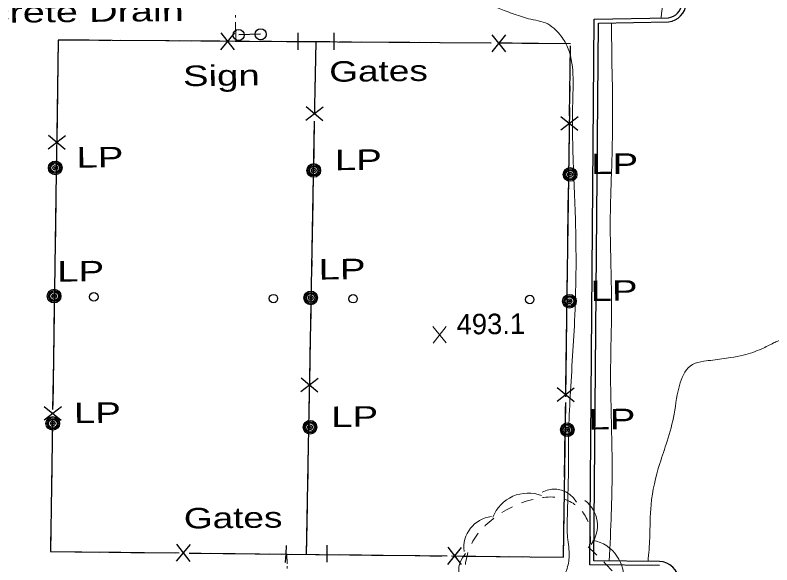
# Model space of a CAD drawing. Extents: x 2362213 to 2366494, y 6968794 to 6978110.
# Drawn here: x 2364059.7 to 2364237.1, y 6972028.3 to 6972157.2 of the extents above; entities that cross this region are included whole.
import ezdxf

# ---------------------------------------------------------------- set-up
doc = ezdxf.new("R2010")
doc.units = 0
doc.header["$LTSCALE"] = 1.9
for name, pattern in [('DOTTED', [1.5, 0.3, -1.2]), ('LONG_DASH_SHORT_DASH', [9.9, 6, -1.2, 1.5, -1.2]), ('SHORT_DASHED', [2.7, 1.5, -1.2])]:
    doc.linetypes.add(name, pattern=pattern)
for name, color, linetype, lineweight in [('13', 7, 'Continuous', 13), ('17', 7, 'Continuous', 25), ('2', 7, 'Continuous', 25), ('20', 7, 'Continuous', 25), ('21', 7, 'Continuous', 25), ('28', 7, 'Continuous', 13), ('29', 7, 'Continuous', 13), ('31', 7, 'Continuous', 25), ('35', 7, 'Continuous', 13)]:
    doc.layers.add(name, color=color, linetype=linetype, lineweight=lineweight)

msp = doc.modelspace()

# ---------------------------------------------------------------- linework, layer by layer
at = {"layer": '13'}
for p, q in [((2364111.329, 6972155.527), (2364111.377, 6972151.527)), ((2364123.43, 6972028.555), (2364123.338, 6972030.825))]:
    msp.add_line(p, q, dxfattribs=at)
at = {"layer": '13', "linetype": 'DOTTED'}
for points in [[(2364110.001, 6972194.146), (2364120.962, 6972182.64), (2364120.484, 6972160.274), (2364111.286, 6972160.077), (2364111.382, 6972151.057)], [(2364214.461, 6972024.613), (2364193.147, 6972026), (2364189.473, 6972021.205), (2364123.705, 6972021.739), (2364123.338, 6972030.825)]]:
    msp.add_lwpolyline(points, dxfattribs=at)
at = {"layer": '17'}
for p, q in [((2364111.063, 6972153.034), (2364107.841, 6972149.053)), ((2364107.863, 6972153.054), (2364111.041, 6972149.034)), ((2364174.66, 6972152.58), (2364171.438, 6972148.609)), ((2364171.47, 6972152.599), (2364174.638, 6972148.579)), ((2364171.249, 6972150.637), (2364111.252, 6972151.056)), ((2364130.144, 6972150.926), (2364129.867, 6972135.933)), ((2364189.852, 6972150.504), (2364174.849, 6972150.612)), ((2364189.673, 6972133.572), (2364189.906, 6972150.015)), ((2364127.829, 6972132.563), (2364131.889, 6972135.692)), ((2364127.888, 6972135.764), (2364131.829, 6972132.491)), ((2364191.645, 6972133.341), (2364187.605, 6972130.192)), ((2364191.606, 6972130.14), (2364187.644, 6972133.393)), ((2364129.801, 6972132.332), (2364128.692, 6972072.337)), ((2364067.459, 6972129.068), (2364071.41, 6972125.805)), ((2364188.798, 6972069.981), (2364189.627, 6972129.971)), ((2364067.41, 6972125.867), (2364071.46, 6972129.006)), ((2364069.372, 6972125.636), (2364068.463, 6972065.645)), ((2364126.654, 6972068.979), (2364130.714, 6972072.097)), ((2364126.714, 6972072.179), (2364130.655, 6972068.907)), ((2364128.626, 6972068.738), (2364127.918, 6972030.768)), ((2364190.771, 6972069.74), (2364186.729, 6972066.601)), ((2364190.731, 6972066.549), (2364186.769, 6972069.801)), ((2364066.445, 6972062.275), (2364070.495, 6972065.414)), ((2364066.495, 6972065.476), (2364070.446, 6972062.213)), ((2364097.522, 6972029.149), (2364100.765, 6972033.11)), ((2364100.723, 6972029.109), (2364097.564, 6972033.139)), ((2364161.122, 6972028.424), (2364164.364, 6972032.395)), ((2364164.322, 6972028.395), (2364161.164, 6972032.425)), ((2364100.945, 6972031.081), (2364160.943, 6972030.403))]:
    msp.add_line(p, q, dxfattribs=at)
at = {"layer": '17', "linetype": 'LONG_DASH_SHORT_DASH'}
msp.add_line((2364130.144, 6972150.926), (2364127.918, 6972030.768), dxfattribs=at)
at = {"layer": '17'}
for points in [[(2364126.011, 6972149.066), (2364126.002, 6972151.066), (2364125.993, 6972153.066)], [(2364134.364, 6972153.076), (2364134.363, 6972151.076), (2364134.362, 6972149.076)], [(2364107.651, 6972151.082), (2364069.767, 6972151.351), (2364069.428, 6972129.237)], [(2364164.543, 6972030.357), (2364188.258, 6972030.093), (2364188.753, 6972066.38)], [(2364068.407, 6972062.044), (2364067.949, 6972031.447), (2364097.343, 6972031.117)], [(2364123.087, 6972028.842), (2364123.198, 6972030.843), (2364123.309, 6972032.844)], [(2364132.728, 6972032.914), (2364132.737, 6972030.914), (2364132.746, 6972028.914)]]:
    msp.add_lwpolyline(points, dxfattribs=at)
at = {"layer": '17', "linetype": 'LONG_DASH_SHORT_DASH'}
msp.add_lwpolyline([(2364189.852, 6972150.504), (2364069.767, 6972151.351), (2364067.949, 6972031.447), (2364188.258, 6972030.093), (2364189.906, 6972150.015)], dxfattribs=at)
at = {"layer": '2'}
for points in [[(2364210.737, 6972028.167), (2364194.395, 6972028.311), (2364195.466, 6972156.228), (2364212.884, 6972156.604)], [(2364210.748, 6972029.127), (2364195.366, 6972029.26), (2364196.415, 6972155.287), (2364212.904, 6972155.644)]]:
    msp.add_lwpolyline(points, dxfattribs=at)
for centre, radius, start, end in [((2364212.41, 6972160.191), 3.614, 276.18661, 356.00812), ((2364212.41, 6972160.191), 4.574, 276.18661, 356.00812), ((2364210.375, 6972024.056), 5.085, 7.18498, 85.79573)]:
    msp.add_arc(centre, radius, start, end, dxfattribs=at)
at = {"layer": '20'}
for centre, radius in [((2364069.062, 6972121.393), 1.6), ((2364069.062, 6972121.393), 1.3), ((2364069.062, 6972121.393), 1), ((2364129.671, 6972120.79), 1.6), ((2364129.671, 6972120.79), 1.3), ((2364069.062, 6972121.393), 0.539), ((2364069.062, 6972121.393), 0.192), ((2364129.671, 6972120.79), 1), ((2364129.671, 6972120.79), 0.539), ((2364129.671, 6972120.79), 0.192), ((2364189.783, 6972119.862), 1.6), ((2364189.783, 6972119.862), 1.3), ((2364189.783, 6972119.862), 1), ((2364189.783, 6972119.862), 0.539), ((2364189.783, 6972119.862), 0.192), ((2364068.799, 6972091.319), 1.6), ((2364068.799, 6972091.319), 1.3), ((2364068.799, 6972091.319), 1), ((2364068.799, 6972091.319), 0.539), ((2364078.091, 6972091.147), 1), ((2364128.966, 6972090.902), 1.6), ((2364128.966, 6972090.902), 1.3), ((2364128.966, 6972090.902), 1), ((2364068.799, 6972091.319), 0.192), ((2364120.217, 6972090.728), 1), ((2364128.966, 6972090.902), 0.539), ((2364128.966, 6972090.902), 0.192), ((2364138.888, 6972090.716), 1), ((2364180.322, 6972090.521), 1), ((2364189.646, 6972090.119), 1.6), ((2364189.646, 6972090.119), 1.3), ((2364189.646, 6972090.119), 1), ((2364189.646, 6972090.119), 0.539), ((2364189.646, 6972090.119), 0.192), ((2364068.483, 6972061.484), 1.6), ((2364068.483, 6972061.484), 1.3), ((2364068.483, 6972061.484), 1), ((2364068.483, 6972061.484), 0.539), ((2364068.483, 6972061.484), 0.192), ((2364128.804, 6972060.579), 1.6), ((2364128.804, 6972060.579), 1.3), ((2364128.804, 6972060.579), 1), ((2364128.804, 6972060.579), 0.539), ((2364128.804, 6972060.579), 0.192), ((2364189.133, 6972059.983), 1.6), ((2364189.133, 6972059.983), 1.3), ((2364189.133, 6972059.983), 1), ((2364189.133, 6972059.983), 0.539), ((2364189.133, 6972059.983), 0.192)]:
    msp.add_circle(centre, radius, dxfattribs=at)
at = {"layer": '21'}
msp.add_line((2364117.226, 6972152.733), (2364112.097, 6972152.554), dxfattribs=at)
for centre in [(2364117.217, 6972152.722), (2364112.088, 6972152.544)]:
    msp.add_circle(centre, 1.3, dxfattribs=at)
at = {"layer": '29'}
for centre, radius, start, end in [((2364186.112, 6972040.189), 5.889, 28.74305, 118.74305), ((2364179.948, 6972036.298), 8.839, 68.94138, 158.94138), ((2364188.833, 6972037.522), 7.369, 323.00429, 53.00429), ((2364172.23, 6972032.337), 7.369, 96.88937, 186.88937), ((2364193.498, 6972025.384), 8.839, 349.43512, 79.43512), ((2364169.555, 6972026.926), 5.889, 136.99099, 226.99099)]:
    msp.add_arc(centre, radius, start, end, dxfattribs=at)
at = {"layer": '29', "linetype": 'SHORT_DASHED'}
msp.add_spline([(2364193.995, 6972032.548), (2364202.775, 6972023.042), (2364208.45, 6972003.624), (2364204.259, 6971991.114), (2364199.061, 6971985.644), (2364199.653, 6971976.01), (2364204.763, 6971960.237), (2364194.81, 6971943.811), (2364177.187, 6971948.135), (2364166.75, 6971965.755), (2364170.786, 6971984.024), (2364170.369, 6971996.262), (2364166.915, 6972014.51), (2364166.041, 6972031.781), (2364180.718, 6972043.563), (2364189.382, 6972043.355), (2364193.928, 6972038.578), (2364194.541, 6972033.013)], degree=3, dxfattribs=at)
at = {"layer": '31', "lineweight": 13}
for p, q in [((2364160.757, 6972080.354), (2364157.64, 6972084.205)), ((2364157.677, 6972080.325), (2364160.72, 6972084.234))]:
    msp.add_line(p, q, dxfattribs=at)
at = {"layer": '35'}
for points in [[(2364217.742, 6972294.317), (2364217.129, 6972289.46), (2364216.268, 6972279.113), (2364215.551, 6972268.304), (2364214.768, 6972258.098), (2364214.429, 6972244.393), (2364214.09, 6972231.659), (2364214.046, 6972206.827), (2364213.077, 6972182.627), (2364212.025, 6972164.976), (2364211.145, 6972156.567)], [(2364091.503, 6972164.529), (2364100.213, 6972163.581), (2364103.636, 6972163.174), (2364111.989, 6972162.874), (2364117.079, 6972163.992), (2364122.147, 6972164.31), (2364134.281, 6972163.866), (2364140.814, 6972163.568), (2364150.574, 6972163.601), (2364160.268, 6972163.213), (2364161.13, 6972163.001), (2364164.749, 6972162.056), (2364166.909, 6972161.166), (2364171.204, 6972159.567), (2364174.356, 6972158.297), (2364178.128, 6972156.963), (2364180.024, 6972156.361), (2364184.536, 6972155.134), (2364186.43, 6972153.702), (2364188.648, 6972150.833), (2364190.4, 6972137.039), (2364190.488, 6972123.558), (2364191.078, 6972107.794), (2364190.85, 6972085.511), (2364189.749, 6972066.71), (2364189.45, 6972058.226), (2364189.401, 6972050.775), (2364189.125, 6972038.772), (2364189.158, 6972035.323), (2364189.581, 6972030.845), (2364189.093, 6972027.491), (2364188.001, 6972023.531), (2364188.282, 6972020.274), (2364184.272, 6972020.125), (2364174.98, 6972020.217), (2364168.57, 6972020.326), (2364162.308, 6972020.406), (2364155.958, 6972019.286)], [(2364199.535, 6972155.357), (2364199.546, 6972149.947), (2364199.753, 6972137.678), (2364199.568, 6972122.495), (2364199.212, 6972108.402), (2364199.525, 6972088.124), (2364199.294, 6972074.58), (2364199.628, 6972054.162), (2364199.46, 6972040.381), (2364198.946, 6972029.225)], [(2364239.855, 6972081.057), (2364238.518, 6972080.785), (2364237.522, 6972080.335), (2364234.755, 6972078.988), (2364230.408, 6972077.456), (2364227.493, 6972076.909), (2364225.386, 6972076.578), (2364221.121, 6972076.048), (2364218.479, 6972075.283), (2364215.63, 6972070.976), (2364214.18, 6972063.652), (2364212.54, 6972057.305), (2364210.83, 6972052.049), (2364208.771, 6972042.41), (2364208.465, 6972034.585), (2364208.067, 6972029.151)]]:
    msp.add_spline(points, degree=3, dxfattribs=at)

# ---------------------------------------------------------------- texts
at = {"layer": '17', "width": 1.35}
for p in [(2364133.333, 6972141.566), (2364099.24, 6972036.826)]:
    msp.add_text('Gates', height=4.8, rotation=0.546, dxfattribs=at).set_placement(p)
at = {"layer": '20', "width": 1.4}
for p in [(2364069.062, 6972121.392), (2364129.671, 6972120.789), (2364189.783, 6972119.861), (2364064.557, 6972094.668), (2364125.855, 6972095.153), (2364189.647, 6972090.12), (2364068.483, 6972061.485), (2364128.804, 6972060.579), (2364189.133, 6972059.983)]:
    msp.add_text('  LP', height=4.8, rotation=0.546, dxfattribs=at).set_placement(p)
at = {"layer": '21', "width": 1.4}
msp.add_text('Sign', height=4.8, rotation=0.546, dxfattribs=at).set_placement((2364099.042, 6972140.549))
at = {"layer": '28', "width": 1.45}
msp.add_text('Concrete Drain', height=4.8, rotation=0.546, dxfattribs=at).set_placement((2364036.639, 6972155.226))
at = {"layer": '31'}
msp.add_text('493.1', height=4.8, rotation=0.546, dxfattribs=at).set_placement((2364163.199, 6972082.318))

doc.saveas('drawing.dxf')
